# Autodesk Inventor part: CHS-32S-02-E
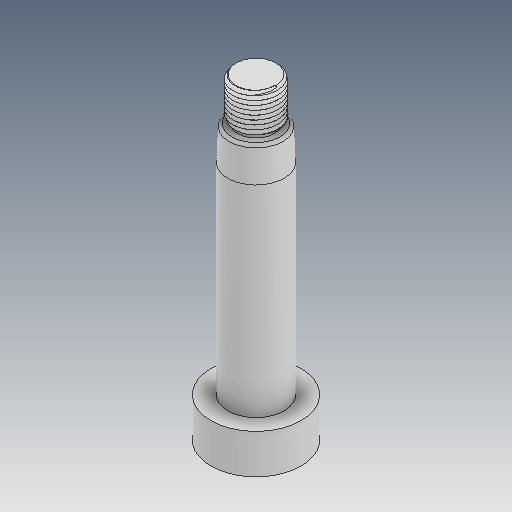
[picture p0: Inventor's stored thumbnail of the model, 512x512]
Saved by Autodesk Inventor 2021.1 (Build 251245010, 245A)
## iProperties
Created: 2021-05
Part Number: CHS-32S-02-E
Material: Ogólny
Document SubType Name: Modeling
Designer: user
Density: 1 g/cm^3
Appearance: Domyślna
Author: user
Revision Number: ÈÎºÎ
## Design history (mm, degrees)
feature "ÊäÈë1"
feature "ÊäÈë2"
node "Bryła1"
node "Bryła2"
